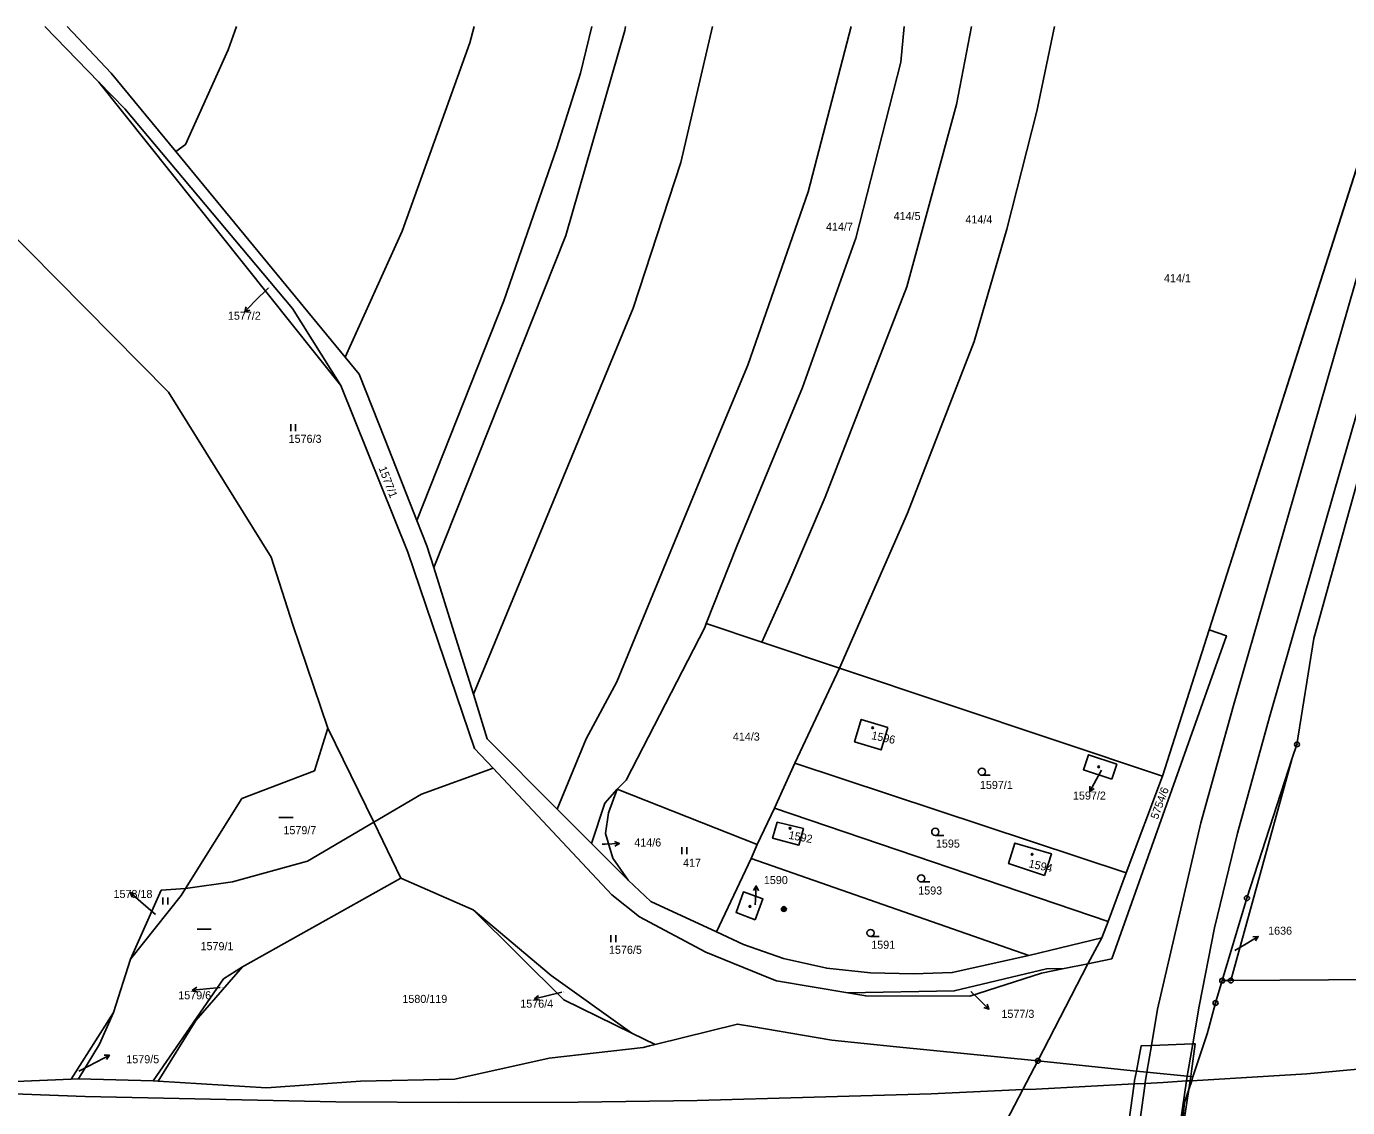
# Model space of a CAD drawing. Extents: x -737240 to -735272, y -1119606 to -1117878.
# Drawn here: x -736144.6 to -735865.3, y -1118106.8 to -1117878.3 of the extents above; entities that cross this region are included whole.
import ezdxf

# ---------------------------------------------------------------- set-up
doc = ezdxf.new("R2010")
doc.units = 0
for name, color, linetype in [('Level 1', 7, 'Continuous'), ('Level 13', 7, 'Continuous'), ('Level 16', 7, 'Continuous'), ('Level 18', 7, 'Continuous'), ('Level 19', 7, 'Continuous'), ('Level 25', 7, 'Continuous'), ('Level 4', 7, 'Continuous')]:
    doc.layers.add(name, color=color, linetype=linetype)

msp = doc.modelspace()

# ---------------------------------------------------------------- linework, layer by layer
at = {"layer": 'Level 1'}
for p, q in [((-736129.25, -1117890.14), (-736140.636, -1117878.325)), ((-735894.53, -1118005.85), (-735855.46, -1117883.38)), ((-736078.08, -1117954.21), (-736129.25, -1117890.14)), ((-736077.16, -1117948.22), (-736112.96, -1117904.75)), ((-736000.86, -1118004.55), (-735989.09, -1118008.49)), ((-735904.4, -1118036.81), (-735894.53, -1118005.85)), ((-735989.09, -1118008.49), (-735972.71, -1118013.97)), ((-736080.82, -1118026.64), (-736071.15, -1118046.52)), ((-735877, -1118033), (-735890, -1118080)), ((-735986.47, -1118043.59), (-735982.13, -1118034.03)), ((-735982.13, -1118034.03), (-735912.1, -1118057.24)), ((-735904.4, -1118036.81), (-735912.1, -1118057.24)), ((-735990.08, -1118051.27), (-736019.72, -1118039.55)), ((-736025.1, -1118051.05), (-736032.34, -1118043.79)), ((-735986.47, -1118043.59), (-735915.91, -1118067.52)), ((-736071.15, -1118046.52), (-736065.39, -1118058.35)), ((-736017.4, -1118058.78), (-736025.1, -1118051.05)), ((-735998.67, -1118069.72), (-735991.39, -1118054.17)), ((-735991.39, -1118054.17), (-735932.67, -1118074.71)), ((-735912.1, -1118057.24), (-735915.91, -1118067.52)), ((-736065.39, -1118058.35), (-736098.85, -1118077.08)), ((-736065.39, -1118058.35), (-736050.16, -1118065.06)), ((-735915.91, -1118067.52), (-735917.23, -1118070.96)), ((-735917.23, -1118070.96), (-735932.67, -1118074.71)), ((-735920.18, -1118076.43), (-735917.23, -1118070.96)), ((-736122.53, -1118075.48), (-736126.14, -1118086.71)), ((-735930.76, -1118096.97), (-735920.18, -1118076.43)), ((-735920.18, -1118076.43), (-735925.2, -1118077.46)), ((-735890, -1118080), (-735891.8, -1118080.01)), ((-735890, -1118080), (-735744.34, -1118079.05)), ((-736126.14, -1118086.71), (-736135.1, -1118100.8)), ((-736016.58, -1118091.08), (-736011.65, -1118093.48)), ((-735930.76, -1118096.97), (-735933.98, -1118103.05)), ((-735930.76, -1118096.97), (-735909.95, -1118099.11)), ((-735909.95, -1118099.11), (-735907.72, -1118099.34)), ((-735907.72, -1118099.34), (-735899.19, -1118100.21)), ((-736133.56, -1118100.73), (-736117.76, -1118101.18)), ((-736117.76, -1118101.18), (-736116.69, -1118101.24)), ((-735898.86, -1118103), (-735898.26, -1118101.16)), ((-735898.46, -1118100.29), (-735897.99, -1118100.33)), ((-735898.26, -1118101.16), (-735897.99, -1118100.33)), ((-735933.98, -1118103.05), (-735939.72, -1118114.11))]:
    msp.add_line(p, q, dxfattribs=at)
for points in [[(-736112.96, -1117904.75), (-736126.61, -1117888.17), (-736135.912, -1117878.325)], [(-736135.912, -1117878.325), (-736126.61, -1117888.17), (-736112.96, -1117904.75), (-736077.16, -1117948.22), (-736074.2, -1117951.81), (-736068.74, -1117965.67), (-736062.02, -1117982.73), (-736059.91, -1117988.08), (-736058.46, -1117992.68), (-736053.76, -1118007.62), (-736050.09, -1118019.48), (-736047.17, -1118028.89), (-736032.34, -1118043.79), (-736025.1, -1118051.05), (-736017.4, -1118058.78), (-736012.56, -1118063.3), (-735998.67, -1118069.72)], [(-736100.154, -1117878.325), (-736101.9, -1117883.28), (-736110.92, -1117903.29), (-736112.96, -1117904.75)], [(-736049.949, -1117878.325), (-736050.84, -1117881.79), (-736065.16, -1117921.62), (-736077.16, -1117948.22)], [(-736025.015, -1117878.325), (-736027.45, -1117888.24), (-736032.42, -1117904.01), (-736043.66, -1117936.29), (-736062.02, -1117982.73)], [(-736017.9, -1117878.325), (-736018.1, -1117879.18), (-736030.53, -1117922.54), (-736058.46, -1117992.68)], [(-735999.552, -1117878.325), (-736006.23, -1117907.08), (-736016.3, -1117937.85), (-736040.05, -1117995.33), (-736050.09, -1118019.48)], [(-735970.211, -1117878.325), (-735979.3, -1117913.3), (-735992.04, -1117949.94), (-735999.9, -1117968.67), (-736019.73, -1118016.82), (-736026.27, -1118028.87), (-736032.34, -1118043.79)], [(-735959.02, -1117878.325), (-735959.76, -1117885.88), (-735969.25, -1117923.11), (-735980.54, -1117954.65), (-735994.4, -1117988.19), (-736000.86, -1118004.55)], [(-735944.792, -1117878.325), (-735947.95, -1117894.86), (-735958.5, -1117933.39), (-735975.71, -1117977.81), (-735983.44, -1117995.76), (-735989.09, -1118008.49)], [(-735972.71, -1118013.97), (-735958.36, -1117981.23), (-735944.22, -1117944.92), (-735937.34, -1117921.15), (-735930.96, -1117896.21), (-735927.286, -1117878.325)], [(-735853.848, -1117878.325), (-735855.46, -1117883.38), (-735894.53, -1118005.85), (-735904.4, -1118036.81), (-735972.71, -1118013.97)], [(-736129.25, -1117890.14), (-736123.74, -1117895.75), (-736088.31, -1117937.95), (-736078.08, -1117954.21)], [(-736177.04, -1117898.36), (-736155.91, -1117913.84), (-736114.53, -1117955.61), (-736092.85, -1117990.52), (-736088.26, -1118004.83), (-736080.82, -1118026.64)], [(-736062.02, -1117982.73), (-736068.74, -1117965.67), (-736074.2, -1117951.81), (-736077.16, -1117948.22)], [(-736045.9, -1118035.13), (-736049.85, -1118030.91), (-736063.97, -1117989.45), (-736078.08, -1117954.21)], [(-735863.03, -1117973.65), (-735872.41, -1118007.67), (-735876.01, -1118030.08), (-735877, -1118033)], [(-736058.46, -1117992.68), (-736059.91, -1117988.08), (-736062.02, -1117982.73)], [(-736050.09, -1118019.48), (-736053.76, -1118007.62), (-736058.46, -1117992.68)], [(-736019.72, -1118039.55), (-736017.79, -1118037.64), (-736001.19, -1118005.35), (-736000.86, -1118004.55)], [(-735894.53, -1118005.85), (-735890.93, -1118007.12), (-735915.15, -1118075.39), (-735920.18, -1118076.43)], [(-735972.71, -1118013.97), (-735982.13, -1118034.03), (-735986.47, -1118043.59), (-735990.08, -1118051.27)], [(-735982.13, -1118034.03), (-735972.71, -1118013.97), (-735904.4, -1118036.81)], [(-736032.34, -1118043.79), (-736047.17, -1118028.89), (-736050.09, -1118019.48)], [(-736080.82, -1118026.64), (-736083.67, -1118035.67), (-736099, -1118041.53), (-736110.96, -1118060.54)], [(-735962.46, -1118026.54), (-735963.89, -1118031.23), (-735969.52, -1118029.52), (-735968.11, -1118024.81), (-735962.46, -1118026.54)], [(-735915.16, -1118037.44), (-735914.1, -1118034.28), (-735920.07, -1118032.28), (-735921.13, -1118035.44), (-735915.16, -1118037.44)], [(-735891.8, -1118080.01), (-735886.59, -1118062.57), (-735877, -1118033)], [(-736071.15, -1118046.52), (-736061.03, -1118040.57), (-736045.9, -1118035.13)], [(-735970.92, -1118082.6), (-735986.04, -1118080.05), (-735987.27, -1118079.55), (-736000.98, -1118073.97), (-736014.97, -1118066.51), (-736020.84, -1118061.87), (-736045.9, -1118035.13)], [(-736019.72, -1118039.55), (-736022.28, -1118042.51), (-736025.1, -1118051.05)], [(-736017.4, -1118058.78), (-736020.58, -1118054.09), (-736022.17, -1118048.92), (-736021.53, -1118044.52), (-736019.72, -1118039.55)], [(-735991.39, -1118054.17), (-735990.08, -1118051.27), (-735986.47, -1118043.59)], [(-736110.96, -1118060.54), (-736101.01, -1118059.1), (-736085.14, -1118054.74), (-736071.15, -1118046.52)], [(-735985.9, -1118046.5), (-735980.31, -1118047.85), (-735981.28, -1118051.35), (-735986.83, -1118049.9), (-735985.9, -1118046.5)], [(-735990.08, -1118051.27), (-735991.39, -1118054.17), (-735998.67, -1118069.72), (-736012.56, -1118063.3), (-736017.4, -1118058.78)], [(-735929.38, -1118057.76), (-735936.97, -1118055.28), (-735935.62, -1118050.94), (-735927.91, -1118053.23), (-735929.38, -1118057.76)], [(-736122.53, -1118075.48), (-736111.87, -1118061.98), (-736110.96, -1118060.54)], [(-736110.96, -1118060.54), (-736116.04, -1118060.89), (-736122.53, -1118075.48)], [(-735990.55, -1118067.13), (-735994.57, -1118065.6), (-735993.02, -1118061.24), (-735988.88, -1118062.73), (-735990.55, -1118067.13)], [(-736050.16, -1118065.06), (-736030.98, -1118084.09), (-736016.58, -1118091.08)], [(-736016.58, -1118091.08), (-736033.62, -1118078.89), (-736050.16, -1118065.06)], [(-735932.67, -1118074.71), (-735948.87, -1118078.31), (-735957.03, -1118078.6), (-735966.13, -1118078.37), (-735975.4, -1118077.4), (-735984.54, -1118075.35), (-735992.99, -1118072.36), (-735998.67, -1118069.72)], [(-736098.85, -1118077.08), (-736102.92, -1118079.63), (-736117.76, -1118101.18)], [(-736116.69, -1118101.24), (-736108.76, -1118088.47), (-736098.85, -1118077.08)], [(-735925.2, -1118077.46), (-735929.98, -1118078.44), (-735945.12, -1118083.26), (-735967.16, -1118083.23), (-735970.92, -1118082.6)], [(-735970.92, -1118082.6), (-735948.43, -1118082.18), (-735928.94, -1118077.53), (-735925.2, -1118077.46)], [(-735897.99, -1118100.33), (-735895.01, -1118091.23), (-735894.66, -1118089.96), (-735893.21, -1118084.73), (-735891.8, -1118080.01)], [(-736133.56, -1118100.73), (-736129.14, -1118093.41), (-736126.14, -1118086.71)], [(-736011.65, -1118093.48), (-735994.27, -1118089.2), (-735991.21, -1118089.72), (-735974.32, -1118092.59), (-735960.63, -1118093.97), (-735930.76, -1118096.97)], [(-736251.5, -1118094.24), (-736233.09, -1118095.66), (-736213.25, -1118097.77), (-736193.2, -1118099.56), (-736173.47, -1118100.33), (-736153.58, -1118101.62), (-736135.1, -1118100.8)], [(-736116.69, -1118101.24), (-736093.8, -1118102.69), (-736073.92, -1118101.23), (-736054.01, -1118100.81), (-736034.06, -1118096.38), (-736014.2, -1118094.11), (-736012.83, -1118093.77), (-736011.65, -1118093.48)], [(-736135.1, -1118100.8), (-736133.66, -1118100.73), (-736133.56, -1118100.73)], [(-735899.19, -1118100.21), (-735898.52, -1118100.28), (-735898.46, -1118100.29)], [(-735900.45, -1118112.69), (-735899.76, -1118105.75), (-735898.86, -1118103)]]:
    msp.add_lwpolyline(points, dxfattribs=at)
at = {"layer": 'Level 13'}
for points in [[(-736135.912, -1117878.325), (-736126.61, -1117888.17), (-736112.96, -1117904.75), (-736077.16, -1117948.22), (-736074.2, -1117951.81), (-736068.74, -1117965.67), (-736062.02, -1117982.73), (-736059.91, -1117988.08), (-736058.46, -1117992.68), (-736053.76, -1118007.62), (-736050.09, -1118019.48), (-736047.17, -1118028.89), (-736032.34, -1118043.79), (-736025.1, -1118051.05), (-736017.4, -1118058.78), (-736012.56, -1118063.3), (-735998.67, -1118069.72), (-735991.39, -1118054.17), (-735990.08, -1118051.27), (-735986.47, -1118043.59), (-735982.13, -1118034.03), (-735972.71, -1118013.97), (-735904.4, -1118036.81), (-735894.53, -1118005.85), (-735855.46, -1117883.38)], [(-735855.46, -1117883.38), (-735894.53, -1118005.85), (-735904.4, -1118036.81), (-735972.71, -1118013.97), (-735982.13, -1118034.03), (-735986.47, -1118043.59), (-735990.08, -1118051.27), (-735991.39, -1118054.17), (-735998.67, -1118069.72), (-736012.56, -1118063.3), (-736017.4, -1118058.78), (-736025.1, -1118051.05), (-736032.34, -1118043.79), (-736047.17, -1118028.89), (-736050.09, -1118019.48), (-736053.76, -1118007.62), (-736058.46, -1117992.68), (-736059.91, -1117988.08), (-736062.02, -1117982.73), (-736068.74, -1117965.67), (-736074.2, -1117951.81), (-736077.16, -1117948.22), (-736112.96, -1117904.75), (-736126.61, -1117888.17), (-736135.912, -1117878.325)]]:
    msp.add_lwpolyline(points, dxfattribs=at)
at = {"layer": 'Level 16'}
for points in [[(-736093.4, -1117933.55), (-736096.31, -1117936.49), (-736098.421, -1117938.622)], [(-736097.362, -1117938.263), (-736098.421, -1117938.622), (-736098.072, -1117937.559)], [(-735917.3, -1118035.52), (-735918.35, -1118037.42), (-735919.8, -1118040.047)], [(-735918.879, -1118039.413), (-735919.8, -1118040.047), (-735919.754, -1118038.929)], [(-736022.87, -1118051.2), (-736022.2, -1118051.17), (-736019.203, -1118051.031)], [(-736020.225, -1118050.578), (-736019.203, -1118051.031), (-736020.179, -1118051.577)], [(-735990.849, -1118060.967), (-735990.299, -1118059.994), (-735989.85, -1118061.018)], [(-735990.5, -1118063.97), (-735990.45, -1118062.99), (-735990.299, -1118059.994)], [(-736122.171, -1118062.393), (-736122.591, -1118061.357), (-736121.51, -1118061.643)], [(-736117.3, -1118066.02), (-736120.34, -1118063.34), (-736122.591, -1118061.357)], [(-735889.15, -1118073.62), (-735886.77, -1118072.21), (-735884.189, -1118070.681)], [(-735885.304, -1118070.76), (-735884.189, -1118070.681), (-735884.795, -1118071.621)], [(-736108.427, -1118082.418), (-736109.468, -1118082.011), (-736108.517, -1118081.422)], [(-736103.62, -1118081.48), (-736106.48, -1118081.74), (-736109.468, -1118082.011)], [(-736031.4, -1118082.47), (-736034.24, -1118083.16), (-736037.156, -1118083.864)], [(-736036.067, -1118084.115), (-736037.156, -1118083.864), (-736036.301, -1118083.143)], [(-735944.94, -1118082.31), (-735943.28, -1118083.92), (-735941.128, -1118086.01)], [(-735941.497, -1118084.955), (-735941.128, -1118086.01), (-735942.194, -1118085.672)], [(-736133.45, -1118099.11), (-736129.66, -1118097.15), (-736126.995, -1118095.772)], [(-736128.113, -1118095.787), (-736126.995, -1118095.772), (-736127.654, -1118096.676)]]:
    msp.add_lwpolyline(points, dxfattribs=at)
at = {"layer": 'Level 25'}
for p, q in [((-736088.687, -1117962.405), (-736088.687, -1117963.905)), ((-736087.665, -1117963.905), (-736087.665, -1117962.405)), ((-735940.818, -1118036.61), (-735942.6, -1118036.61)), ((-736091.17, -1118045.52), (-736088.17, -1118045.52)), ((-735950.668, -1118049.31), (-735952.45, -1118049.31)), ((-736005.997, -1118051.765), (-736005.997, -1118053.265)), ((-736004.975, -1118053.265), (-736004.975, -1118051.765)), ((-735953.638, -1118059.16), (-735955.42, -1118059.16)), ((-736115.687, -1118062.445), (-736115.687, -1118063.945)), ((-736114.665, -1118063.945), (-736114.665, -1118062.445)), ((-736108.47, -1118069.14), (-736105.47, -1118069.14)), ((-736021.007, -1118070.405), (-736021.007, -1118071.905)), ((-736019.985, -1118071.905), (-736019.985, -1118070.405)), ((-735964.348, -1118070.69), (-735966.13, -1118070.69))]:
    msp.add_line(p, q, dxfattribs=at)
for centre, major_axis, ratio in [((-735965.68, -1118026.57), (0.18, 0), 0.9848078), ((-735876.01, -1118030.08), (0.516, 0), 0.9848078), ((-735876.01, -1118030.08), (0.0375, 0), 0.9848078), ((-735942.6, -1118035.854), (0.764, 0), 0.9894236), ((-735917.93, -1118034.82), (0.18, 0), 0.9848078), ((-735983.14, -1118047.79), (0.18, 0), 0.9848078), ((-735952.45, -1118048.554), (0.764, 0), 0.9894236), ((-735931.98, -1118053.31), (0.18, 0), 0.9848078), ((-735955.42, -1118058.404), (0.764, 0), 0.9894236), ((-735886.59, -1118062.57), (0.516, 0), 0.9848078), ((-735886.59, -1118062.57), (0.0375, 0), 0.9848078), ((-735991.63, -1118064.33), (0.18, 0), 0.9848078), ((-735984.45, -1118064.88), (0.516, 0), 0.9848078), ((-735984.45, -1118064.88), (0.309, 0), 0.9848078), ((-735984.45, -1118064.88), (0.155, 0), 0.9848078), ((-735966.13, -1118069.934), (0.764, 0), 0.9894236), ((-735891.8, -1118080.01), (0.516, 0), 0.9848078), ((-735891.8, -1118080.01), (0.0375, 0), 0.9848078), ((-735890, -1118080), (0.516, 0), 0.9848078), ((-735890, -1118080), (0.0375, 0), 0.9848078), ((-735893.21, -1118084.73), (0.516, 0), 0.9848078), ((-735893.21, -1118084.73), (0.0375, 0), 0.9848078), ((-735930.76, -1118096.97), (0.516, 0), 0.9848078), ((-735930.76, -1118096.97), (0.0375, 0), 0.9848078)]:
    msp.add_ellipse(centre, major_axis=major_axis, ratio=ratio, dxfattribs=at)
at = {"layer": 'Level 4'}
for p, q in [((-735907.72, -1118099.34), (-735906.76, -1118093.72)), ((-735898.04, -1118093.4), (-735906.76, -1118093.72)), ((-735910.42, -1118101.84), (-735911.97, -1118112.95)), ((-735908.12, -1118101.72), (-735910.42, -1118101.84)), ((-735909.67, -1118112.9), (-735908.12, -1118101.72)), ((-735899.34, -1118101.22), (-735901.04, -1118112.71)), ((-735899.19, -1118100.21), (-735899.34, -1118101.22)), ((-735898.59, -1118101.18), (-735899.34, -1118101.22)), ((-735898.86, -1118103), (-735898.59, -1118101.18)), ((-735898.59, -1118101.18), (-735898.46, -1118100.29)), ((-735898.26, -1118101.16), (-735898.59, -1118101.18)), ((-735900.31, -1118112.69), (-735898.86, -1118103))]:
    msp.add_line(p, q, dxfattribs=at)
for points in [[(-735898.04, -1118093.4), (-735896.67, -1118085.41), (-735893.44, -1118068.88), (-735888.61, -1118048.85), (-735881.84, -1118024.35), (-735868.14, -1117976.68), (-735854.57, -1117929.61), (-735844.29, -1117895.87), (-735837.95, -1117880.61), (-735835.97, -1117878.325)], [(-735906.76, -1118093.72), (-735905.46, -1118086.07), (-735896.31, -1118046.67), (-735889.43, -1118021.85), (-735875.7, -1117974.2), (-735862.2, -1117927.45), (-735849.98, -1117885.08)], [(-735906.76, -1118093.72), (-735908.96, -1118093.8), (-735909.95, -1118099.11)], [(-735898.04, -1118093.4), (-735899.01, -1118099.02), (-735899.19, -1118100.21)], [(-735898.46, -1118100.29), (-735898.29, -1118099.16), (-735897.51, -1118093.38), (-735898.04, -1118093.4)], [(-735745.82, -1118093.99), (-735766, -1118093.8), (-735791.17, -1118094.01), (-735812.13, -1118094.52), (-735822.68, -1118095.26), (-735848.46, -1118097.37), (-735873.93, -1118099.68), (-735898.26, -1118101.16)], [(-735933.98, -1118103.05), (-735953.29, -1118103.9), (-736002.75, -1118105.32), (-736027.95, -1118105.72), (-736053.13, -1118105.79), (-736079.13, -1118105.63), (-736132.16, -1118104.51), (-736158.54, -1118103.51), (-736190.64, -1118101.98), (-736215.89, -1118100.45), (-736241.6, -1118098.57), (-736251.56, -1118097.78)], [(-735909.95, -1118099.11), (-735910.32, -1118101.12), (-735910.42, -1118101.84)], [(-735908.12, -1118101.72), (-735908.1, -1118101.56), (-735907.72, -1118099.34)], [(-735933.98, -1118103.05), (-735931.14, -1118102.93), (-735910.42, -1118101.84)], [(-735899.34, -1118101.22), (-735904.27, -1118101.52), (-735908.12, -1118101.72)]]:
    msp.add_lwpolyline(points, dxfattribs=at)

# ---------------------------------------------------------------- texts
at = {"layer": 'Level 16'}
for s, p in [('1577/2', (-736101.97, -1117940.32)), ('1597/2', (-735923.35, -1118041.75)), ('414/6', (-736016.075, -1118051.66)), ('1590', (-735988.69, -1118059.6)), ('1578/18', (-736126.145, -1118062.54)), ('1636', (-735882.1, -1118070.3)), ('1579/6', (-736112.46, -1118083.95)), ('1576/4', (-736040.17, -1118085.73)), ('1577/3', (-735938.47, -1118087.88)), ('1579/5', (-736123.44, -1118097.47))]:
    msp.add_text(s, height=1.7, dxfattribs=at).set_placement(p)
at = {"layer": 'Level 18'}
for s, height, p in [('414/5', 1.7, (-735961.26, -1117919.25)), ('414/4', 1.7, (-735946.08, -1117919.96)), ('414/7', 1.7, (-735975.55, -1117921.5)), ('414/1', 1.7, (-735904.12, -1117932.38)), ('1577/2', 0.1, (-736093.25, -1117933.55)), ('1576/3', 1.7, (-736089.13, -1117966.34)), ('414/3', 1.7, (-735995.24, -1118029.28)), ('1597/1', 1.7, (-735943.02, -1118039.5)), ('1579/7', 1.7, (-736090.23, -1118049.06)), ('414/6', 0.1, (-736022.87, -1118051.2)), ('1595', 1.7, (-735952.32, -1118051.89)), ('417', 1.7, (-736005.76, -1118055.94)), ('1593', 1.7, (-735956.06, -1118061.81)), ('1578/18', 0.1, (-736117.125, -1118066.02)), ('1579/1', 1.7, (-736107.75, -1118073.57)), ('1591', 1.7, (-735965.99, -1118073.27)), ('1576/5', 1.7, (-736021.42, -1118074.34)), ('1636', 0.1, (-735889.15, -1118073.62)), ('1579/6', 0.1, (-736103.47, -1118081.48)), ('1580/119', 1.7, (-736065.09, -1118084.72)), ('1576/4', 0.1, (-736031.25, -1118082.47)), ('1577/3', 0.1, (-735944.79, -1118082.31)), ('1579/5', 0.1, (-736133.3, -1118099.11))]:
    msp.add_text(s, height=height, dxfattribs=at).set_placement(p)
for s, rotation, p in [('1577/1', 291.02724, (-736070.145, -1117971.67)), ('5754/6', 69.91902, (-735905.43, -1118046.04))]:
    msp.add_text(s, height=1.7, rotation=rotation, dxfattribs=at).set_placement(p)
at = {"layer": 'Level 19'}
for s, rotation, p in [('1596', 347.89167, (-735966.062, -1118028.936)), ('1592', 349.27893, (-735983.552, -1118050.015)), ('1594', 347.46669, (-735932.83, -1118056.03))]:
    msp.add_text(s, height=1.7, rotation=rotation, dxfattribs=at).set_placement(p)
for s, p in [('1597/2', (-735917.125, -1118035.52)), ('1590', (-735990.375, -1118063.97))]:
    msp.add_text(s, height=0.1, dxfattribs=at).set_placement(p)

doc.saveas('drawing.dxf')
